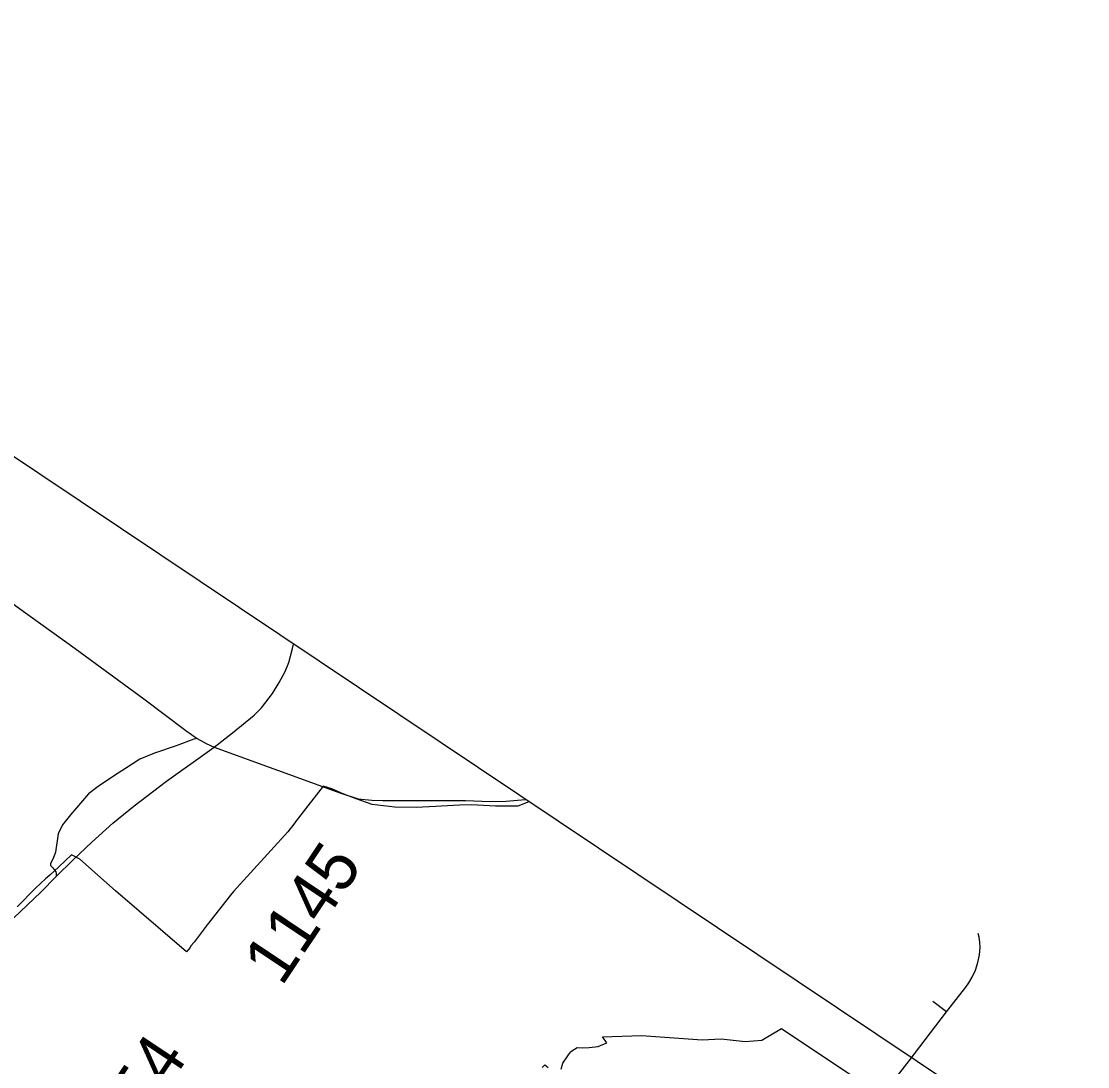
# Model space of a CAD drawing. Extents: x 1716282 to 1717158, y 799307 to 801078.
# Drawn here: x 1716655.2 to 1716809.1, y 800924.3 to 801075.1 of the extents above; entities that cross this region are included whole.
import ezdxf

# ---------------------------------------------------------------- set-up
doc = ezdxf.new("R2010")
doc.units = 0
for name, color, linetype in [('Exist Boundary Political City Limit New', 7, 'Continuous'), ('Exist Road Non-System Type 51', 7, 'Continuous'), ('Exist Road Secondary Type 51 Attributed', 7, 'Continuous'), ('Old_Level_1', 7, 'Continuous'), ('Prop DSN Text', 7, 'Continuous')]:
    doc.layers.add(name, color=color, linetype=linetype)

msp = doc.modelspace()

# ---------------------------------------------------------------- linework, layer by layer
at = {"layer": 'Exist Boundary Political City Limit New'}
msp.add_line((1716728.47, 800962.51), (1716728.47, 800962.51), dxfattribs=at)
for points in [[(1716728.47, 800962.51), (1716726.89, 800961.89), (1716723.64, 800961.89), (1716720.19, 800962.09), (1716718.47, 800962.01), (1716715.02, 800961.85), (1716712.2, 800961.71), (1716709.14, 800961.72), (1716705.86, 800962.13), (1716703.67, 800962.87), (1716701.78, 800963.61), (1716700.04, 800964.38), (1716698.8, 800964.75), (1716695.25, 800960.22), (1716695.05, 800959.96), (1716694.54, 800959.3), (1716693.67, 800958.2), (1716686.33, 800950.08), (1716685.86, 800949.56), (1716685.42, 800949.04), (1716682.06, 800944.76), (1716680.16, 800942.28), (1716679.7, 800941.71), (1716679.57, 800941.5), (1716679.3, 800941.16), (1716679.07, 800940.86), (1716668.83, 800949.66), (1716663.68, 800954.22), (1716662.46, 800954.86), (1716660.65, 800953.13), (1716659.33, 800951.92), (1716658.74, 800951.38), (1716657.28, 800950.03), (1716654.63, 800947.36)], [(1716733.14, 800923.92), (1716733.37, 800924.81), (1716734.2, 800926.01), (1716734.47, 800926.4), (1716734.55, 800926.46), (1716735.44, 800927.04), (1716736.25, 800927), (1716737.16, 800927.06), (1716738.47, 800927.22), (1716739.74, 800927.74), (1716739.08, 800928.59), (1716744.75, 800928.79), (1716753.5, 800928.15), (1716756.24, 800928.32), (1716759.7, 800927.9), (1716762.07, 800928.13), (1716764.91, 800929.8), (1716787.78, 800914.54)], [(1716730.37, 800924.19), (1716730.78, 800924.55), (1716731.27, 800924.17)]]:
    msp.add_lwpolyline(points, dxfattribs=at)
at = {"layer": 'Exist Road Non-System Type 51'}
msp.add_line((1716788.75, 800932.18), (1716786.75, 800933.69), dxfattribs=at)
for points in [[(1716788.75, 800932.18), (1716791.55, 800935.75), (1716791.98, 800936.38), (1716792.44, 800937.2), (1716792.91, 800938.22), (1716793.27, 800939.3), (1716793.51, 800940.41), (1716793.6, 800941.48), (1716793.57, 800942.24), (1716793.46, 800942.97), (1716793.32, 800943.51)], [(1716770.25, 800907.15), (1716770.78, 800908.38), (1716771.37, 800909.46), (1716772.02, 800910.42), (1716773.13, 800911.95), (1716783.37, 800925.12), (1716788.75, 800932.18)]]:
    msp.add_lwpolyline(points, dxfattribs=at)
at = {"layer": 'Exist Road Secondary Type 51 Attributed'}
for points in [[(1716580.65, 801012.65), (1716581.88, 801012.71), (1716592.81, 801012.54), (1716594.8, 801012.5), (1716595.68, 801012.48), (1716600.49, 801012.36), (1716605.3, 801012.13), (1716608.14, 801011.9), (1716610.61, 801011.4), (1716614.88, 801010.34), (1716618.11, 801009.37), (1716626.56, 801006.94), (1716630.75, 801005.64), (1716634.21, 801004.25), (1716635.71, 801003.69), (1716636.54, 801003.34), (1716638.16, 801002.59), (1716642.34, 800999.67), (1716654.61, 800990.64), (1716663.02, 800984.64), (1716672.9, 800977.37), (1716678.98, 800972.79), (1716680.58, 800971.65)], [(1716683.06, 800970.39), (1716685.72, 800972.46), (1716688.82, 800975.03), (1716689.91, 800976.09), (1716691.48, 800978.13), (1716692.44, 800979.71), (1716693.32, 800981.34), (1716693.84, 800982.61), (1716694.38, 800984.65), (1716694.49, 800985.25)], [(1716680.58, 800971.65), (1716680.14, 800971.53), (1716677.57, 800970.61), (1716674.44, 800969.53), (1716672.31, 800968.69), (1716670.42, 800967.43), (1716668.54, 800966.22), (1716666.32, 800964.71), (1716664.93, 800963.67), (1716664.06, 800962.67), (1716662.31, 800960.62), (1716661.19, 800959.2), (1716660.56, 800957.88), (1716660.17, 800955.24), (1716659.8, 800954.34), (1716659.43, 800953.61), (1716659.42, 800953.47), (1716659.46, 800953.31), (1716659.77, 800952.98), (1716660.2, 800952.41), (1716660.26, 800952.16), (1716660.24, 800951.73)], [(1716680.58, 800971.65), (1716681.91, 800970.91), (1716683.06, 800970.39)], [(1716660.24, 800951.73), (1716662.7, 800954.16), (1716665.42, 800956.71), (1716668.44, 800959.41), (1716671.52, 800961.93), (1716675.18, 800964.73), (1716676.17, 800965.49), (1716683.06, 800970.39)], [(1716683.06, 800970.39), (1716701.35, 800963.78), (1716703.86, 800962.95), (1716705.81, 800962.76), (1716707.42, 800962.68), (1716719.35, 800962.72), (1716722.87, 800962.56), (1716725.21, 800962.62), (1716727.96, 800962.85)], [(1716640.65, 800932.45), (1716645.4, 800937.25), (1716654.17, 800945.75), (1716658.03, 800949.47), (1716660.24, 800951.73)]]:
    msp.add_lwpolyline(points, dxfattribs=at)
at = {"layer": 'Prop DSN Text'}
msp.add_lwpolyline([(1716644.27, 800417.02), (1716922.46, 800832.66), (1716560.18, 801075.15), (1716281.98, 800659.5)], close=True, dxfattribs=at)

# ---------------------------------------------------------------- texts
at = {"layer": 'Old_Level_1'}
for s, p in [('1145', (1716692.79, 800935.74)), ('1154', (1716667.59, 800908.03))]:
    msp.add_text(s, height=7.128, rotation=56.2051, dxfattribs=at).set_placement(p)

doc.saveas('drawing.dxf')
